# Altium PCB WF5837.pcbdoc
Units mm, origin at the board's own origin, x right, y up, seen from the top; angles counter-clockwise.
Board outline 16.96 x 16.4 mm, 2 copper layers (Top Layer, Bottom Layer); 1 components, 0 nets, 4 pads, 0 vias.
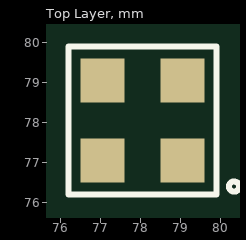
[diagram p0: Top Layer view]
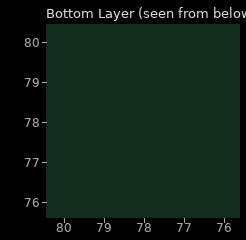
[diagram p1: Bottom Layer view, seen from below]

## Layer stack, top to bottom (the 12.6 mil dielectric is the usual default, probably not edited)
Top Layer: signal copper (thickness not stored)
Dielectric: dielectric 0.32, FR-4, Dk 4.8
Bottom Layer: signal copper (thickness not stored)

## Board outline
86.814,69.85 69.85,69.85 69.85,86.25 86.814,86.25

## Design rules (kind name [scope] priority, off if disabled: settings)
BoardOutlineClearance safeClearance [All] p0: genericclearance=0.254 ignorepadtopadclearanceinfootprint=FALSE except(0: Arc-SplitContinuation Track-SplitContinuation SMDPad-SplitContinuation THPad-SplitContinuation Via-SplitContinuation Fill-SplitContinuation Poly-SplitContinuation Region-SplitContinuation Text-SplitContinuation; 0.152: Track-CutoutEdge SMDPad-CutoutEdge THPad-CutoutEdge Via-CutoutEdge Fill-CutoutEdge Region-CutoutEdge; 0.3: Track-OutlineEdge SMDPad-OutlineEdge THPad-OutlineEdge Via-OutlineEdge Fill-OutlineEdge Region-OutlineEdge Poly-OutlineEdge Text-OutlineEdge)
Clearance safeClearance [All] p1: gap=0.178 ignorepadtopadclearanceinfootprint=FALSE except(0.152: Track-Track Track-SMDPad SMDPad-SMDPad Track-THPad SMDPad-THPad THPad-THPad Track-Via SMDPad-Via THPad-Via Via-Via Track-Fill SMDPad-Fill THPad-Fill Via-Fill Fill-Fill Track-Region SMDPad-Region THPad-Region Via-Region Fill-Region Region-Region Track-Poly SMDPad-Poly THPad-Poly Via-Poly Fill-Poly Region-Poly Poly-Poly Track-Text SMDPad-Text THPad-Text Via-Text Fill-Text Region-Text Poly-Text Text-Text; 0.175: Track-Hole SMDPad-Hole THPad-Hole Via-Hole Fill-Hole Region-Hole Poly-Hole Text-Hole Sheet-Hole; 0.3: Track-Sheet SMDPad-Sheet THPad-Sheet Via-Sheet Fill-Sheet Region-Sheet Poly-Sheet Text-Sheet)
DiffPairsRouting differentialPair [All] p1: maxuncoupledlength=10 minlimit=6 maxlimit=6 mostfreqgap=6 toplayer_minwidth=5 toplayer_prefwidth=10 toplayer_maxwidth=100 bottomlayer_minwidth=5 bottomlayer_prefwidth=10 bottomlayer_maxwidth=100
PasteMaskExpansion pasteMaskExpansion [All] p1: expansion=0
PlaneConnect innerPlane [All] p1: planeconnectstyle=Relief reliefexpansion=0.508 reliefentries=4 reliefconductorwidth=0.254 reliefairgap=0.254
PolygonConnect copperRegion [All] p1: connectstyle=Relief reliefentries=4 reliefconductorwidth=10 polygonreliefangle="90 Angle" airgapwidth=10
RoutingVias viaSize [All] p1: viastyle="Through Hole" holewidth=12.0078 minholewidth=11.811 maxholewidth=236.2204 width=24.0158 minwidth=19.685 maxwidth=393.7008
SolderMaskExpansion solderMaskExpansion [All] p1: useseparateexpansions=TRUE expansion=2 expansionbottom=2
Width trackWidth [All] p1: maxlimit=100 minlimit=5 preferedwidth=10

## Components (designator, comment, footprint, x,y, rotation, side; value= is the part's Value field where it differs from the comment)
? "WF5837" WF5837 78.051,78.051 r0 top

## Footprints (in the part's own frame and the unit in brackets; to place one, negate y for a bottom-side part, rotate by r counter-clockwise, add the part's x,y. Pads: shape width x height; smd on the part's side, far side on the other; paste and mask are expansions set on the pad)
WF5837 [mm]
  rect 1.1x1.1 smd: 1(0.999,-1.001) 2(0.999,0.999) 3(-1.001,0.999) 4(-1.001,-1.001)
  silkscreen extent -1.85,-1.85 2.41,1.85

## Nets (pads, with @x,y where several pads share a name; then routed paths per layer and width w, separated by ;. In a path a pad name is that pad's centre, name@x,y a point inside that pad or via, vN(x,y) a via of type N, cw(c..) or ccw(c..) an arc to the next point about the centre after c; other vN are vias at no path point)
pads on no net: ?.1 ?.2 ?.3 ?.4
